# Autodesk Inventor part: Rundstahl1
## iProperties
Created: 2007-03
Part Number: Rundstahl1
Document SubType Name: Modeling
Designer: Sascha Fleischer
Author: Sascha Fleischer
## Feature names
1. Extrusion1
2. Extrusion2
